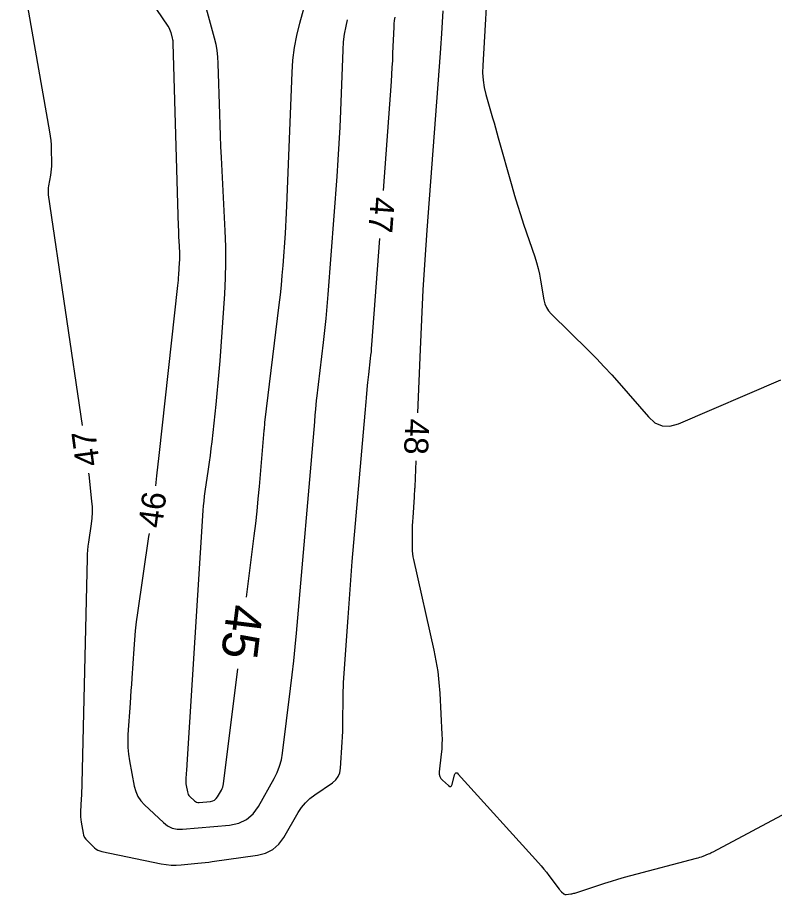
# Model space of a CAD drawing. Extents: x 2384780 to 2405861, y 547869 to 573706.
# Drawn here: x 2389833.8 to 2389896.7, y 552156.8 to 552229.8 of the extents above; entities that cross this region are included whole.
import ezdxf

# ---------------------------------------------------------------- set-up
doc = ezdxf.new("R2010")
doc.units = 0
doc.layers.add('Old_Level_60', color=7, linetype='Continuous')
doc.layers.add('Old_Level_61', color=7, linetype='Continuous')

msp = doc.modelspace()

# ---------------------------------------------------------------- linework, layer by layer
at = {"layer": 'Old_Level_60'}
for points in [[(2389833.773, 552235.5055), (2389836.44125, 552220.2835), (2389836.49625, 552219.929), (2389836.537, 552219.5735), (2389836.5635, 552219.2165), (2389836.576, 552218.858), (2389836.59375, 552217.68525), (2389836.59125, 552217.4345), (2389836.5765, 552217.18475), (2389836.5495, 552216.936), (2389836.51, 552216.68825), (2389836.34775, 552215.808), (2389836.32075, 552215.61925), (2389836.3095, 552215.43025), (2389836.31375, 552215.24075), (2389836.33375, 552215.05125), (2389839.1515, 552195.848)], [(2389841.63025, 552235.97325), (2389846.2715, 552229.0905), (2389846.34925, 552228.9645), (2389846.416, 552228.83325), (2389846.4715, 552228.69725), (2389846.51625, 552228.556), (2389846.64425, 552228.0865), (2389846.6685, 552227.9855), (2389846.68675, 552227.8835), (2389846.699, 552227.7805), (2389846.705, 552227.67675), (2389847.14125, 552212.41225), (2389847.1505, 552212.114), (2389847.16175, 552211.8155), (2389847.1745, 552211.51725), (2389847.189, 552211.219), (2389847.2395, 552210.245), (2389847.247, 552210.03625), (2389847.24825, 552209.82775), (2389847.24325, 552209.619), (2389847.23175, 552209.4105), (2389847.15925, 552208.3805), (2389847.14275, 552208.15975), (2389847.124, 552207.93925), (2389847.103, 552207.719), (2389847.08025, 552207.499), (2389845.5375, 552193.36425), (2389845.34525, 552191.675), (2389845.2415, 552190.83075)], [(2389872.9425, 552234.038), (2389872.46675, 552225.8195), (2389872.45675, 552225.20475), (2389872.498, 552224.5955), (2389872.59075, 552223.992), (2389872.735, 552223.39425), (2389873.28975, 552221.451), (2389873.4085, 552221.0345), (2389873.527, 552220.618), (2389873.645, 552220.20125), (2389873.76275, 552219.7845), (2389874.8905, 552215.787), (2389875.12125, 552214.9885), (2389875.36225, 552214.193), (2389875.61325, 552213.40075), (2389875.8745, 552212.6115), (2389876.79525, 552209.88925), (2389876.9465, 552209.41025), (2389877.07875, 552208.92625), (2389877.19125, 552208.4375), (2389877.28475, 552207.944), (2389877.55775, 552206.32325), (2389877.64025, 552205.9885), (2389877.771, 552205.679), (2389877.94975, 552205.3945), (2389878.17675, 552205.135), (2389881.281, 552202.08175), (2389881.9395, 552201.42125), (2389882.58425, 552200.748), (2389883.21575, 552200.062), (2389883.8335, 552199.36325), (2389886.25425, 552196.57075), (2389886.79925, 552196.08625), (2389887.39625, 552195.8295), (2389888.0455, 552195.8005), (2389888.747, 552195.9995), (2389897.26075, 552199.65875)], [(2389864.2035, 552215.41025), (2389864.87375, 552224.48), (2389864.91425, 552225.0655), (2389864.95, 552225.65125), (2389864.9805, 552226.23725), (2389865.00575, 552226.82375), (2389865.09025, 552228.9915), (2389865.1095, 552229.27475), (2389865.1445, 552229.55575), (2389865.19575, 552229.83425)], [(2389869.15875, 552230.37175), (2389869.04875, 552228.4715), (2389869.02425, 552228.0645), (2389868.998, 552227.6575), (2389868.97, 552227.2505), (2389868.94025, 552226.84375), (2389867.83025, 552212.1085), (2389867.65475, 552209.62825), (2389867.50125, 552207.14675), (2389867.37025, 552204.66375), (2389867.2615, 552202.17975), (2389867.054, 552196.8965)], [(2389844.7115, 552186.86625), (2389844.6765, 552186.61925), (2389843.745, 552180.24975), (2389843.64425, 552179.508), (2389843.559, 552178.765), (2389843.48875, 552178.02), (2389843.43375, 552177.27375), (2389843.279, 552174.833), (2389843.24525, 552174.31), (2389843.21075, 552173.787), (2389843.1755, 552173.264), (2389843.13925, 552172.74125), (2389842.9575, 552170.15075), (2389842.93625, 552169.59675), (2389842.95075, 552169.04475), (2389843.00075, 552168.495), (2389843.0865, 552167.947), (2389843.48775, 552165.82525), (2389843.60525, 552165.38775), (2389843.78525, 552164.98475), (2389844.02825, 552164.616), (2389844.334, 552164.28175), (2389845.90575, 552162.804), (2389846.258, 552162.532), (2389846.641, 552162.349), (2389847.05525, 552162.2555), (2389847.50025, 552162.25125), (2389851.41575, 552162.5945), (2389852.17375, 552162.74525), (2389852.82875, 552163.0555), (2389853.3805, 552163.52575), (2389853.829, 552164.1555), (2389855.12525, 552166.47325), (2389855.37725, 552166.9785), (2389855.577, 552167.50075), (2389855.725, 552168.03975), (2389855.82125, 552168.596), (2389856.488, 552173.96475), (2389856.6255, 552175.11575), (2389856.75225, 552176.268), (2389856.86825, 552177.42125), (2389856.9735, 552178.57575), (2389858.492, 552196.151), (2389858.50875, 552196.34375), (2389858.5255, 552196.5365), (2389858.542, 552196.72925), (2389858.55875, 552196.922), (2389858.61325, 552197.55175), (2389858.62525, 552197.68675), (2389858.63875, 552197.8215), (2389858.65325, 552197.956), (2389858.669, 552198.0905), (2389859.23275, 552202.75525), (2389859.3475, 552203.7555), (2389859.451, 552204.75675), (2389859.5425, 552205.75925), (2389859.6225, 552206.76275), (2389860.34825, 552216.58325), (2389860.44325, 552217.9495), (2389860.52625, 552219.31625), (2389860.5975, 552220.68375), (2389860.65675, 552222.05175), (2389860.85375, 552227.1095), (2389860.8985, 552227.77075), (2389860.98025, 552228.4265), (2389861.0995, 552229.07625), (2389861.2325, 552229.62325)], [(2389839.68475, 552191.884), (2389839.69975, 552191.74975), (2389839.93475, 552189.55575), (2389839.97025, 552189.086), (2389839.976, 552188.6165), (2389839.952, 552188.148), (2389839.8985, 552187.67975), (2389839.67375, 552186.14325), (2389839.63075, 552185.8135), (2389839.59775, 552185.483), (2389839.57475, 552185.15175), (2389839.562, 552184.8195), (2389839.12125, 552166.06075), (2389839.11225, 552165.739), (2389839.10025, 552165.4175), (2389839.08525, 552165.09625), (2389839.06725, 552164.775), (2389839.00375, 552163.72575), (2389838.997, 552163.5015), (2389839.00375, 552163.27775), (2389839.02425, 552163.055), (2389839.05825, 552162.83325), (2389839.224, 552161.934), (2389839.27275, 552161.74875), (2389839.3485, 552161.578), (2389839.451, 552161.42175), (2389839.5805, 552161.28025), (2389840.18275, 552160.71375), (2389840.31725, 552160.60325), (2389840.463, 552160.514), (2389840.62, 552160.446), (2389840.788, 552160.3995), (2389845.714, 552159.38425), (2389846.1325, 552159.314), (2389846.5525, 552159.2755), (2389846.9745, 552159.2685), (2389847.398, 552159.29325), (2389848.7845, 552159.4255), (2389849.08125, 552159.45575), (2389849.37775, 552159.489), (2389849.67375, 552159.52575), (2389849.9695, 552159.56575), (2389853.72225, 552160.095), (2389854.405, 552160.264), (2389854.99825, 552160.56625), (2389855.502, 552161.00125), (2389855.9165, 552161.5695), (2389857.12425, 552163.64325), (2389857.40375, 552164.06825), (2389857.72475, 552164.45475), (2389858.087, 552164.80275), (2389858.49075, 552165.11225), (2389859.96925, 552166.1235), (2389860.2495, 552166.36075), (2389860.4565, 552166.64), (2389860.59025, 552166.9605), (2389860.65075, 552167.32275), (2389860.78625, 552169.489), (2389860.81175, 552169.95325), (2389860.83025, 552170.41775), (2389860.84175, 552170.88225), (2389860.84625, 552171.34725), (2389860.84975, 552173.02425), (2389860.85325, 552173.38325), (2389860.86275, 552173.74225), (2389860.87825, 552174.10125), (2389860.8995, 552174.45975), (2389861.265, 552179.88075), (2389861.34625, 552181.04225), (2389861.43275, 552182.20325), (2389861.52475, 552183.36375), (2389861.62225, 552184.52375), (2389862.68875, 552196.86575), (2389862.7165, 552197.18625), (2389862.744, 552197.5065), (2389862.77175, 552197.827), (2389862.7995, 552198.1475), (2389862.89, 552199.1945), (2389862.91025, 552199.41875), (2389862.9325, 552199.64275), (2389862.95675, 552199.8665), (2389862.98275, 552200.09025), (2389863.14275, 552201.41425), (2389863.1755, 552201.698), (2389863.20475, 552201.98225), (2389863.23075, 552202.26675), (2389863.2535, 552202.55175), (2389863.90875, 552211.421)], [(2389866.897, 552192.8995), (2389866.81275, 552190.7555), (2389866.809, 552190.66975), (2389866.80475, 552190.58425), (2389866.8, 552190.4985), (2389866.7945, 552190.413), (2389866.77575, 552190.1335), (2389866.7715, 552190.0735), (2389866.7675, 552190.01375), (2389866.7635, 552189.95375), (2389866.7595, 552189.894), (2389866.64525, 552188.1985), (2389866.6245, 552187.8495), (2389866.6095, 552187.50025), (2389866.60025, 552187.151), (2389866.59675, 552186.8015), (2389866.59425, 552185.65925), (2389866.60075, 552185.41525), (2389866.6205, 552185.17275), (2389866.654, 552184.93175), (2389866.70125, 552184.69225), (2389868.401, 552177.1655), (2389868.5825, 552176.2745), (2389868.72575, 552175.37825), (2389868.83025, 552174.47675), (2389868.89675, 552173.57), (2389869.07425, 552170.1465), (2389869.087, 552169.7365), (2389869.08225, 552169.327), (2389869.06025, 552168.918), (2389869.02125, 552168.50975), (2389868.8465, 552167.0215), (2389868.84525, 552166.8225), (2389868.8895, 552166.6415), (2389868.97975, 552166.4785), (2389869.116, 552166.33325), (2389869.63525, 552165.88875), (2389869.73725, 552165.823), (2389869.82, 552165.81675), (2389869.884, 552165.87), (2389869.92875, 552165.9825), (2389870.12425, 552166.76725), (2389870.1755, 552166.8985), (2389870.24525, 552166.95525), (2389870.3335, 552166.93775), (2389870.44025, 552166.84625), (2389877.10975, 552159.45), (2389877.333, 552159.19725), (2389877.55025, 552158.93975), (2389877.762, 552158.67775), (2389877.96825, 552158.411), (2389878.82375, 552157.27925), (2389878.87175, 552157.21875), (2389878.92275, 552157.16075), (2389878.9765, 552157.1055), (2389879.033, 552157.053), (2389879.2225, 552156.8855), (2389879.26475, 552156.85475), (2389879.31025, 552156.83475), (2389879.359, 552156.8255), (2389879.41125, 552156.82675), (2389879.79875, 552156.874), (2389879.88125, 552156.88625), (2389879.963, 552156.90225), (2389880.04375, 552156.9225), (2389880.12375, 552156.9465), (2389882.63175, 552157.76825), (2389883.1705, 552157.94025), (2389883.7115, 552158.104), (2389884.255, 552158.2595), (2389884.801, 552158.40675), (2389890.26025, 552159.83375), (2389890.40225, 552159.8735), (2389890.54275, 552159.91775), (2389890.6815, 552159.96675), (2389890.819, 552160.0205), (2389891.26525, 552160.20325), (2389891.36025, 552160.24375), (2389891.454, 552160.28625), (2389891.547, 552160.3315), (2389891.63875, 552160.379), (2389898.17325, 552163.86425)]]:
    msp.add_lwpolyline(points, dxfattribs=at)
at = {"layer": 'Old_Level_61'}
for points in [[(2389852.826, 552181.56425), (2389853.4615, 552186.68075), (2389853.58375, 552187.70325), (2389853.6965, 552188.727), (2389853.7995, 552189.75175), (2389853.893, 552190.7775), (2389854.2955, 552195.43625), (2389854.301, 552195.5015), (2389854.30675, 552195.5665), (2389854.31225, 552195.6315), (2389854.318, 552195.6965), (2389854.33625, 552195.909), (2389854.3405, 552195.95475), (2389854.345, 552196), (2389854.34975, 552196.0455), (2389854.35525, 552196.091), (2389855.5405, 552205.89925), (2389855.634, 552206.71375), (2389855.71825, 552207.52925), (2389855.79275, 552208.3455), (2389855.858, 552209.163), (2389856.05525, 552211.83425), (2389856.09525, 552212.40675), (2389856.13, 552212.9795), (2389856.15975, 552213.55275), (2389856.18475, 552214.126), (2389856.6175, 552225.2275), (2389856.6875, 552226.26675), (2389856.81625, 552227.297), (2389857.0035, 552228.31825), (2389857.2495, 552229.33025), (2389858.4085, 552233.56975)], [(2389849.46375, 552230.56825), (2389850.13075, 552228.12), (2389850.25775, 552227.593), (2389850.353, 552227.06125), (2389850.41625, 552226.52475), (2389850.44775, 552225.98375), (2389850.568, 552221.7705), (2389850.5965, 552220.86775), (2389850.63, 552219.965), (2389850.669, 552219.06275), (2389850.713, 552218.16075), (2389851.029, 552212.047), (2389851.07675, 552210.737), (2389851.0845, 552209.4275), (2389851.05225, 552208.1185), (2389850.98025, 552206.80975), (2389850.5885, 552201.239), (2389850.52, 552200.32725), (2389850.4425, 552199.41625), (2389850.3565, 552198.50625), (2389850.26175, 552197.59675), (2389849.92325, 552194.49575), (2389849.8585, 552193.92575), (2389849.78825, 552193.35625), (2389849.713, 552192.7875), (2389849.63275, 552192.21925), (2389849.3615, 552190.3645), (2389849.3075, 552189.9665), (2389849.2615, 552189.56775), (2389849.22375, 552189.16825), (2389849.19425, 552188.76775), (2389847.85475, 552167.6385), (2389847.84375, 552167.4655), (2389847.83225, 552167.2925), (2389847.8205, 552167.1195), (2389847.8085, 552166.9465), (2389847.769, 552166.38125), (2389847.76425, 552166.2605), (2389847.7675, 552166.14), (2389847.7785, 552166.02), (2389847.797, 552165.9005), (2389847.89825, 552165.366), (2389847.92775, 552165.25575), (2389847.97325, 552165.15425), (2389848.0345, 552165.06125), (2389848.1115, 552164.977), (2389848.489, 552164.622), (2389848.57375, 552164.5565), (2389848.66575, 552164.5125), (2389848.76525, 552164.49025), (2389848.87225, 552164.489), (2389849.82625, 552164.57275), (2389850.0105, 552164.60925), (2389850.1695, 552164.68475), (2389850.30375, 552164.799), (2389850.41275, 552164.952), (2389850.72775, 552165.51525), (2389850.78875, 552165.638), (2389850.8375, 552165.765), (2389850.8735, 552165.896), (2389850.89675, 552166.031), (2389852.0865, 552175.61)]]:
    msp.add_lwpolyline(points, dxfattribs=at)

# ---------------------------------------------------------------- texts
at = {"layer": 'Old_Level_60'}
for s, rotation, p in [('47', 265.774325, (2389863.1645, 552214.91825)), ('48', 267.7506389, (2389866.03525, 552196.43975)), ('47', 97.6590167, (2389840.62125, 552192.58175)), ('46', 82.3860417, (2389845.782, 552187.2475))]:
    msp.add_text(s, height=2, rotation=rotation, dxfattribs=at).set_placement(p)
at = {"layer": 'Old_Level_61'}
msp.add_text('45', height=3, rotation=262.9196111, dxfattribs=at).set_placement((2389851.2515, 552181.0575))

doc.saveas('drawing.dxf')
